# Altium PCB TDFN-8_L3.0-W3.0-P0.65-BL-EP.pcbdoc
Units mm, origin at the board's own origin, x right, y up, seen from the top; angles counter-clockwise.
Board outline 15.85 x 16.59 mm, 2 copper layers (Top Layer, Bottom Layer), stack 0 mm thick; 1 components, 0 nets, 9 pads, 0 vias.
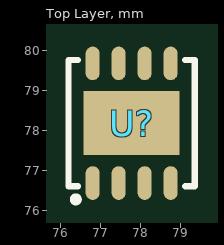
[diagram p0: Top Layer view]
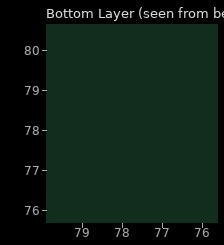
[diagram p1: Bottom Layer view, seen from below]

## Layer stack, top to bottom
Top Layer: signal copper (thickness not stored)
Bottom Layer: signal copper (thickness not stored)

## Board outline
85.702,69.85 69.85,69.85 69.85,86.445 85.702,86.445

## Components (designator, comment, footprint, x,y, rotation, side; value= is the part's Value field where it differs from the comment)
U? "" TDFN-8_L3.0-W3.0-P0.65-BL-EP 77.776,78.18 r0 top

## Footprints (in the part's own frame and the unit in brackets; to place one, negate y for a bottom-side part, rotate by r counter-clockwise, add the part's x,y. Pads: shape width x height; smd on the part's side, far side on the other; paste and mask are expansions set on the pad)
TDFN-8_L3.0-W3.0-P0.65-BL-EP [mm]
  oval 0.35x0.84 smd: 1(-0.975,-1.495) 2(-0.325,-1.495) 3(0.325,-1.495) 4(0.975,-1.495) 5(0.975,1.495) 6(0.325,1.495) 7(-0.325,1.495) 8(-0.975,1.495)
  rect 2.4x1.6 smd: 9(0,0)
  silkscreen extent -1.58,-1.98 1.58,1.58

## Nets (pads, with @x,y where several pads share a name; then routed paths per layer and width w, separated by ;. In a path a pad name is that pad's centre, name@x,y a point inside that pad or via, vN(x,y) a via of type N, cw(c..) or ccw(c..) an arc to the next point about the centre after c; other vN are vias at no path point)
pads on no net: U?.1 U?.2 U?.3 U?.4 U?.5 U?.6 U?.7 U?.8 U?.9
